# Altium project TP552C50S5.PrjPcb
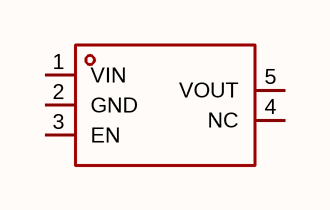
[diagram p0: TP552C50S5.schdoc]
1 sheet, 1 parts. Net scope: global (net labels, ports and power ports of the same name join across sheets).

## Sheet TP552C50S5.schdoc
size 127 x 101 mm

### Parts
U?  tp552c50s5  [SOT-23-5_L2.9-W1.7-P0.95-LS2.8-BL]  (value not drawn)

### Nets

Not connected (* = marked no-connect by the designer): U? 1(VIN) 2(GND) 3(EN) 4(NC) 5(VOUT)

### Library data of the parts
U? = tp552c50s5: 输出极性:正极;工作电压:50V;输出电压:5V;输出电流:200mA;电源纹波抑制比(PSRR):70dB@(100Hz);输出类型:固定;; Manufacturer: TECH PUBLIC(台舟); AddInBom: yes; ModelId: bc68d73ac92c4e0f9e95c23bce7b0706; ModelTransform: 114.173,110.236,0,0,0,0,0,0,0; Output Configuration: 正极; Voltage - Supply: 50V; Output Voltage: 5V; Output Current: 200mA; Voltage Dropout: 660mV@(100mA); standby current: 2uA; Output Type: 固定; Number of Outputs: 1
